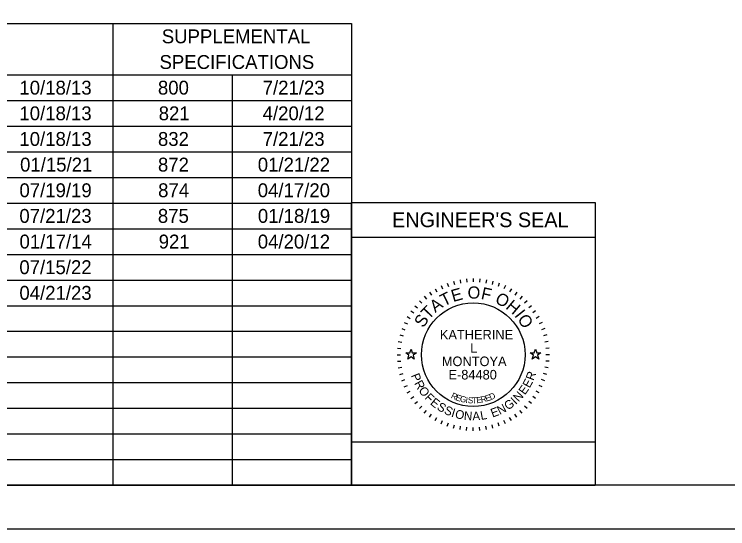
# Model space of a CAD drawing. Extents: x 0 to 34, y 0 to 22.
# Drawn here: x 19.97 to 28.17, y 0 to 5.91 of the extents above; entities that cross this region are included whole.
import ezdxf

# ---------------------------------------------------------------- set-up
doc = ezdxf.new("R2010")
doc.units = 0
for name, color, linetype in [('Default', 7, 'Continuous'), ('GM_X_County', 7, 'Continuous'), ('GM_X_Minor_Lake', 7, 'Continuous'), ('GM_X_Minor_Lake_Text', 7, 'Continuous'), ('GM_X_Minor_River_Text', 7, 'Continuous')]:
    doc.layers.add(name, color=color, linetype=linetype)

msp = doc.modelspace()

# ---------------------------------------------------------------- linework, layer by layer
at = {"layer": 'Default'}
for points in [[(24.4685, 2.02), (24.5154, 2.02), (24.5299, 2.0645), (24.5444, 2.02), (24.5913, 2.02), (24.5534, 1.9924), (24.5679, 1.9478), (24.5299, 1.9754), (24.4919, 1.9478), (24.5064, 1.9924)], [(25.8985, 2.02), (25.9454, 2.02), (25.9599, 2.0645), (25.9744, 2.02), (26.0213, 2.02), (25.9834, 1.9924), (25.9979, 1.9478), (25.9599, 1.9754), (25.9219, 1.9478), (25.9364, 1.9924)]]:
    msp.add_lwpolyline(points, close=True, dxfattribs=at)
at = {"layer": 'GM_X_County'}
msp.add_lwpolyline([(0, 0), (34, 0), (34, 22), (0, 22)], close=True, dxfattribs=at)
at = {"layer": 'GM_X_Minor_Lake'}
for p, q in [((10.15, 5.8046), (23.8449, 5.8046)), ((21.1059, 5.8046), (21.1059, 0.5)), ((23.8449, 5.8046), (23.8449, 0.5)), ((10.15, 5.2152), (23.8449, 5.2152)), ((22.4754, 5.2152), (22.4754, 0.5)), ((10.15, 4.9205), (23.8449, 4.9205)), ((10.15, 4.6258), (23.8449, 4.6258)), ((10.15, 4.3311), (23.8449, 4.3311)), ((10.15, 4.0364), (23.8449, 4.0364)), ((10.15, 3.7417), (23.8449, 3.7417)), ((10.15, 3.447), (23.8449, 3.447)), ((10.15, 3.1523), (23.8449, 3.1523)), ((10.15, 2.8576), (23.8449, 2.8576)), ((10.15, 2.5629), (23.8449, 2.5629)), ((10.15, 2.2682), (23.8449, 2.2682)), ((10.15, 1.9735), (23.8449, 1.9735)), ((10.15, 1.6788), (23.8449, 1.6788)), ((10.15, 1.3841), (23.8449, 1.3841)), ((10.15, 1.0894), (23.8449, 1.0894)), ((10.15, 0.7947), (23.8449, 0.7947)), ((10.15, 0.5), (23.8449, 0.5))]:
    msp.add_line(p, q, dxfattribs=at)
at = {"layer": 'GM_X_Minor_Lake_Text'}
for p, q in [((23.8449, 0.5), (23.8449, 3.75)), ((23.8449, 3.75), (26.6449, 3.75)), ((26.6449, 3.75), (26.6449, 0.5)), ((23.8449, 3.35), (26.6449, 3.35)), ((25.1687, 2.8717), (25.1721, 2.8318)), ((25.2449, 2.875), (25.2449, 2.835)), ((25.3212, 2.8717), (25.3177, 2.8318)), ((24.8751, 2.793), (24.892, 2.7568)), ((24.9457, 2.8222), (24.9593, 2.7846)), ((25.0185, 2.8452), (25.0288, 2.8065)), ((25.093, 2.8617), (25.0999, 2.8223)), ((25.3969, 2.8617), (25.3899, 2.8223)), ((25.4714, 2.8452), (25.461, 2.8065)), ((25.5442, 2.8222), (25.5305, 2.7846)), ((25.6147, 2.793), (25.5978, 2.7568)), ((24.743, 2.7168), (24.766, 2.684)), ((24.8074, 2.7578), (24.8274, 2.7231)), ((25.6824, 2.7578), (25.6624, 2.7231)), ((25.7468, 2.7168), (25.7239, 2.684)), ((24.6825, 2.6703), (24.7082, 2.6396)), ((25.8074, 2.6703), (25.7816, 2.6396)), ((24.5746, 2.5624), (24.6053, 2.5367)), ((24.6262, 2.6187), (24.6545, 2.5904)), ((25.8636, 2.6187), (25.8354, 2.5904)), ((25.9152, 2.5624), (25.8846, 2.5367)), ((24.5282, 2.5019), (24.5609, 2.4789)), ((25.9617, 2.5019), (25.9289, 2.4789)), ((24.4871, 2.4375), (24.5218, 2.4175)), ((26.0027, 2.4375), (25.9681, 2.4175)), ((24.4227, 2.2993), (24.4603, 2.2856)), ((24.4519, 2.3698), (24.4882, 2.3529)), ((26.0379, 2.3698), (26.0017, 2.3529)), ((26.0672, 2.2993), (26.0296, 2.2856)), ((24.3997, 2.2265), (24.4384, 2.2161)), ((26.0901, 2.2265), (26.0515, 2.2161)), ((24.3832, 2.1519), (24.4226, 2.145)), ((26.1066, 2.1519), (26.0672, 2.145)), ((24.3733, 2.0763), (24.4131, 2.0728)), ((26.1166, 2.0763), (26.0767, 2.0728)), ((24.3699, 2), (24.4099, 2)), ((26.1199, 2), (26.0799, 2)), ((24.3733, 1.9237), (24.4131, 1.9272)), ((26.1166, 1.9237), (26.0767, 1.9272)), ((24.3832, 1.8481), (24.4226, 1.855)), ((26.1066, 1.8481), (26.0672, 1.855)), ((24.3997, 1.7735), (24.4384, 1.7839)), ((26.0901, 1.7735), (26.0515, 1.7839)), ((24.4227, 1.7007), (24.4603, 1.7144)), ((24.4519, 1.6302), (24.4882, 1.6471)), ((26.0379, 1.6302), (26.0017, 1.6471)), ((26.0672, 1.7007), (26.0296, 1.7144)), ((24.4871, 1.5625), (24.5218, 1.5825)), ((26.0027, 1.5625), (25.9681, 1.5825)), ((24.5282, 1.4981), (24.5609, 1.5211)), ((25.9617, 1.4981), (25.9289, 1.5211)), ((24.5746, 1.4376), (24.6053, 1.4633)), ((24.6262, 1.3813), (24.6545, 1.4096)), ((25.8636, 1.3813), (25.8354, 1.4096)), ((25.9152, 1.4376), (25.8846, 1.4633)), ((24.6825, 1.3297), (24.7082, 1.3604)), ((24.743, 1.2832), (24.766, 1.316)), ((25.7468, 1.2832), (25.7239, 1.316)), ((25.8074, 1.3297), (25.7816, 1.3604)), ((24.8074, 1.2422), (24.8274, 1.2769)), ((24.8751, 1.207), (24.892, 1.2432)), ((25.6147, 1.207), (25.5978, 1.2432)), ((25.6824, 1.2422), (25.6624, 1.2769)), ((24.9457, 1.1778), (24.9593, 1.2154)), ((25.0185, 1.1548), (25.0288, 1.1935)), ((25.093, 1.1383), (25.0999, 1.1777)), ((25.1687, 1.1283), (25.1721, 1.1682)), ((25.2449, 1.125), (25.2449, 1.165)), ((25.3212, 1.1283), (25.3177, 1.1682)), ((25.3969, 1.1383), (25.3899, 1.1777)), ((25.4714, 1.1548), (25.461, 1.1935)), ((25.5442, 1.1778), (25.5305, 1.2154)), ((23.8449, 0.5), (26.6449, 0.5))]:
    msp.add_line(p, q, dxfattribs=at)
msp.add_lwpolyline([(23.8449, 0.5), (23.8449, 1), (26.6449, 1), (26.6449, 0.5)], close=True, dxfattribs=at)
msp.add_circle((25.2449, 2), 0.595, dxfattribs=at)
at = {"layer": 'GM_X_Minor_River_Text'}
msp.add_lwpolyline([(1.5, 21.5), (33.5, 21.5), (33.5, 0.5), (1.5, 0.5)], close=True, dxfattribs=at)

# ---------------------------------------------------------------- texts
at = {"layer": 'GM_X_Minor_Lake'}
for s, height, p in [('SUPPLEMENTAL', 0.159485, (21.6667, 5.5775)), ('SPECIFICATIONS', 0.159485, (21.6406, 5.2828)), ('10/18/13', 0.15949, (20.031, 4.9881)), ('800', 0.15949, (21.6225, 4.9881)), ('7/21/23', 0.15949, (22.8257, 4.9881)), ('10/18/13', 0.15949, (20.031, 4.6934)), ('821', 0.15949, (21.6312, 4.6934)), ('4/20/12', 0.15949, (22.8252, 4.6934)), ('10/18/13', 0.15949, (20.031, 4.3987)), ('832', 0.15949, (21.6229, 4.3987)), ('7/21/23', 0.15949, (22.8257, 4.3987)), ('01/15/21', 0.15949, (20.0388, 4.104)), ('872', 0.15949, (21.6229, 4.104)), ('01/21/22', 0.15949, (22.7694, 4.104)), ('07/19/19', 0.15949, (20.0316, 3.8093)), ('874', 0.15949, (21.6247, 3.8093)), ('04/17/20', 0.15949, (22.7691, 3.8093)), ('07/21/23', 0.15949, (20.031, 3.5146)), ('875', 0.15949, (21.6218, 3.5146)), ('01/18/19', 0.15949, (22.7705, 3.5146)), ('01/17/14', 0.15949, (20.0323, 3.2199)), ('921', 0.15949, (21.6312, 3.2199)), ('04/20/12', 0.15949, (22.7694, 3.2199)), ('07/15/22', 0.15949, (20.0305, 2.9252)), ('04/21/23', 0.15949, (20.031, 2.6305))]:
    msp.add_text(s, height=height, dxfattribs=at).set_placement(p)
at = {"layer": 'GM_X_Minor_Lake_Text'}
for s, height, p in [("ENGINEER'S SEAL", 0.17, (24.3125, 3.465)), ('KATHERINE', 0.11, (24.8613, 2.1749)), ('L', 0.11, (25.2094, 2.0216)), ('MONTOYA', 0.11, (24.8839, 1.8684)), ('E-84480', 0.11, (24.9599, 1.7151))]:
    msp.add_text(s, height=height, dxfattribs=at).set_placement(p)
for s, height, rotation, p in [('T', 0.14, 25.71674, (24.9066, 2.5518)), ('E', 0.14, 15.75706, (25.0133, 2.6038)), ('O', 0.14, 359.78119, (25.1796, 2.6443)), ('F', 0.14, 347.43619, (25.326, 2.6417)), ('O', 0.14, 332.25863, (25.4847, 2.6015)), ('A', 0.14, 36.47472, (24.8083, 2.4781)), ('H', 0.14, 319.91363, (25.6081, 2.5361)), ('T', 0.14, 46.4344, (24.7332, 2.3964)), ('S', 0.14, 57.19238, (24.673, 2.3014)), ('I', 0.14, 308.36695, (25.7114, 2.4483)), ('O', 0.14, 303.14906, (25.7471, 2.4089)), ('R', 0.1, 69.23216, (25.9369, 1.6954)), ('P', 0.1, 291.49398, (24.5272, 1.7621)), ('E', 0.1, 61.99508, (25.8926, 1.6098)), ('R', 0.1, 298.73106, (24.5639, 1.6717)), ('E', 0.1, 54.75801, (25.8383, 1.5314)), ('O', 0.1, 306.46664, (24.6104, 1.5883)), ('F', 0.1, 314.7068, (24.6792, 1.4983)), ('R', 0.07, 334.48695, (24.9824, 1.5051)), ('D', 0.07, 23.30524, (25.4459, 1.477)), ('N', 0.1, 47.02243, (25.7651, 1.4508)), ('E', 0.1, 321.43929, (24.7427, 1.4348)), ('E', 0.07, 341.03996, (25.0356, 1.4801)), ('G', 0.07, 347.47515, (25.0864, 1.4618)), ('I', 0.07, 353.78581, (25.154, 1.4468)), ('S', 0.07, 356.89262, (25.1807, 1.4429)), ('T', 0.07, 3.00609, (25.2306, 1.4387)), ('E', 0.07, 6.01169, (25.2839, 1.4412)), ('R', 0.07, 11.91844, (25.3374, 1.4474)), ('E', 0.07, 17.68363, (25.3947, 1.4602)), ('G', 0.1, 35.04687, (25.643, 1.357)), ('I', 0.1, 43.28703, (25.7318, 1.4214)), ('S', 0.1, 328.67637, (24.8192, 1.3752)), ('S', 0.1, 335.91345, (24.9013, 1.3266)), ('E', 0.1, 20.07421, (25.4661, 1.277)), ('N', 0.1, 27.31129, (25.5494, 1.3075)), ('I', 0.1, 343.15053, (24.9856, 1.2897)), ('O', 0.1, 346.88592, (25.0288, 1.2751)), ('N', 0.1, 355.12608, (25.1337, 1.2517)), ('A', 0.1, 2.86166, (25.2372, 1.2437)), ('L', 0.1, 10.09874, (25.3343, 1.249))]:
    msp.add_text(s, height=height, rotation=rotation, dxfattribs=at).set_placement(p)

doc.saveas('drawing.dxf')
